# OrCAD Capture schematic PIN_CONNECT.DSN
size A
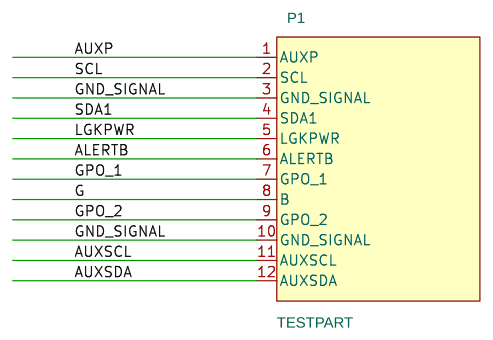
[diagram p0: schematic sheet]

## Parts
P1  TESTPART

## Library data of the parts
P1 = TESTPART

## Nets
GND_SIGNAL: P1.3(GND_SIGNAL) P1.10(GND_SIGNAL)
ALERTB: P1.6(ALERTB)
AUXP: P1.1(AUXP)
AUXSCL: P1.11(AUXSCL)
AUXSDA: P1.12(AUXSDA)
G: P1.8(B)
GPO_1: P1.7(GPO_1)
GPO_2: P1.9(GPO_2)
LGKPWR: P1.5(LGKPWR)
SCL: P1.2(SCL)
SDA1: P1.4(SDA1)
